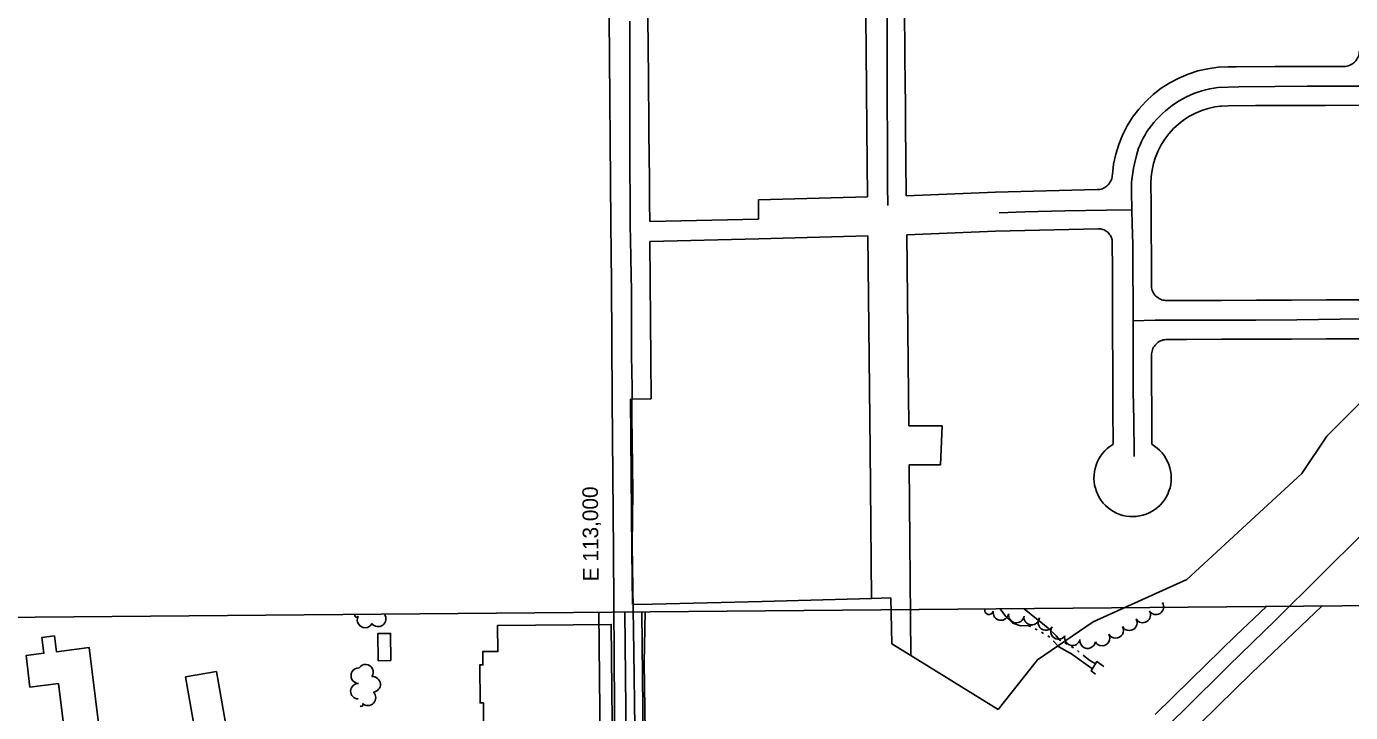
# Model space of a CAD drawing. Extents: x -2233 to 187241, y 4582 to 150524.
# Drawn here: x 112255 to 113957, y 59941 to 60823 of the extents above; entities that cross this region are included whole.
import ezdxf

# ---------------------------------------------------------------- set-up
doc = ezdxf.new("R2010")
doc.units = 0
for name, color, linetype in [('60', 7, 'Continuous'), ('BLDG', 7, 'Continuous'), ('CULVERT', 7, 'Continuous'), ('GE_X_CL_2000', 7, 'Continuous'), ('GRID', 7, 'Continuous'), ('INTERSTATE', 7, 'Continuous'), ('ROAD', 7, 'Continuous'), ('RW_X_Fee_RW', 7, 'Continuous'), ('TREES', 7, 'Continuous'), ('WATER', 7, 'Continuous')]:
    doc.layers.add(name, color=color, linetype=linetype)

msp = doc.modelspace()

# ---------------------------------------------------------------- linework, layer by layer
at = {"layer": '60'}
msp.add_line((109991.1, 60043.6), (114990.9, 60087.2), dxfattribs=at)
at = {"layer": 'BLDG'}
for points in [[(113008.4, 59888.4), (113006.8, 60054.3), (112860.7, 60052.9), (112861, 60019.4), (112841.6, 60019.3), (112841.8, 60002.2), (112837.7, 60002.2), (112838.2, 59953.3), (112842.3, 59953.4), (112842.7, 59912.5)], [(112323.8, 59752.8), (112295.8, 59978.3), (112259.2, 59973.7), (112254.2, 60014.3), (112277.2, 60017.2), (112274.7, 60037.5), (112290.8, 60039.5), (112293.3, 60019.1), (112335.5, 60024.4), (112351.4, 59896.2)]]:
    msp.add_lwpolyline(points, dxfattribs=at)
for points in [[(112723.4, 60007.8), (112722.9, 60042.7), (112706.6, 60042.5), (112707.1, 60007.6)], [(112499, 59993.6), (112511.8, 59920.6), (112472.2, 59913.6), (112459.4, 59986.7)]]:
    msp.add_lwpolyline(points, close=True, dxfattribs=at)
at = {"layer": 'CULVERT'}
msp.add_lwpolyline([(113640, 60000.1), (113631.1, 60006.5), (113624.1, 59994.4), (113629.7, 59990.2)], dxfattribs=at)
at = {"layer": 'GE_X_CL_2000'}
for points in [[(113361.5, 60852.7), (113361.8, 60818.3), (113361.5, 60783.6), (113361.4, 60745.1), (113361.8, 60710), (113362.1, 60693.8), (113362.2, 60664.6), (113362.2, 60618.9), (113362.5, 60593.1)], [(113030.5, 60830.1), (113030.8, 60787.7), (113030.8, 60743.9), (113030.7, 60700.9), (113030.7, 60644.3), (113031.2, 60597), (113031.2, 60566.1), (113031.6, 60550.3), (113032, 60524.8), (113033, 60482.9), (113032.6, 60442.8), (113033, 60399.9), (113033.5, 60359), (113033.4, 60331.5), (113033.4, 60322.1), (113034.7, 60225), (113033.8, 60156.2), (113036, 60018.9), (113036.9, 59922.4), (113037.7, 59833.1), (113038, 59732.7), (113039.2, 59659.9), (113041.5, 59583.1), (113041.4, 59538.4)], [(113676.2, 60587.4), (113675.7, 60610.6), (113675.8, 60616.7), (113676, 60622.7), (113676.6, 60628.7), (113677.3, 60634.7), (113678.3, 60640.7), (113679.5, 60646.6), (113682.1, 60657.2), (113683.5, 60661.8), (113685, 60666.4), (113686.8, 60670.9), (113688.7, 60675.3), (113690.9, 60679.6), (113693.2, 60683.8), (113695.7, 60687.9), (113698.4, 60691.9), (113701.3, 60695.8), (113704.4, 60699.5), (113707.9, 60703.6), (113711.7, 60707.4), (113715.5, 60711.2), (113719.6, 60714.7), (113723.7, 60718.1), (113728, 60721.4), (113732.5, 60724.4), (113737, 60727.3), (113741.6, 60730), (113746.4, 60732.4), (113751.2, 60734.6), (113756.1, 60736.7), (113761.1, 60738.6), (113766.1, 60740.2), (113771.3, 60741.7), (113776.4, 60742.9), (113781.7, 60743.9), (113786.9, 60744.7), (113813.8, 60745.5), (113860.1, 60746.1), (113901.9, 60746.2), (113945.8, 60746.2), (113975.7, 60746.4)], [(113505.6, 60583.3), (113538.5, 60584.7), (113590, 60586.1), (113643.6, 60587), (113676.2, 60587.4)], [(113676.2, 60587.4), (113676.5, 60569.4), (113677.6, 60542.9), (113677.6, 60524.8), (113677.5, 60505.2), (113678.1, 60473.9), (113677.8, 60444.6)], [(113677.8, 60444.6), (113706.1, 60445.6), (113747.9, 60445.3), (113835.8, 60445.4), (113888.2, 60446.1), (113944.1, 60446.6), (113991, 60447), (114010.2, 60446.1), (114026.6, 60446.2), (114078.5, 60446.5), (114086.5, 60446.8), (114094.5, 60447.3), (114102.5, 60448.1), (114110.4, 60449.2), (114117.4, 60451.1), (114124.2, 60453.7), (114130.9, 60457), (114137.2, 60460.8), (114143.2, 60465.2), (114148.7, 60470), (114153.7, 60475.3)], [(113677.8, 60444.6), (113677.9, 60401.4), (113678.1, 60357.4), (113678.5, 60331.5), (113678.6, 60320.8), (113679.1, 60270.1)], [(113973.9, 60171.5), (113918.6, 60116.8), (113861.4, 60060.3), (113800.5, 60000.9), (113743.9, 59944.7), (113689.6, 59892), (113636.5, 59840.6), (113573.6, 59779.7), (113509.2, 59718), (113438.7, 59653.3), (113379, 59599.4), (113344.7, 59567.8), (113332.6, 59556.6), (113316, 59541.3), (113301.8, 59528.7), (113254.1, 59486.6), (113202.8, 59441.5), (113191.5, 59431.1), (113123.8, 59370.9), (113063.3, 59318.1), (113037.7, 59296.4), (113006.2, 59273.3), (112963.6, 59238.9), (112917.8, 59201.4)]]:
    msp.add_lwpolyline(points, dxfattribs=at)
at = {"layer": 'GRID'}
for p, q in [((114990.9, 60087.2), (109991.1, 60043.6)), ((112991, 60069.8), (113014.5, 57372.1))]:
    msp.add_line(p, q, dxfattribs=at)
at = {"layer": 'INTERSTATE'}
for points in [[(113849.6, 60077.3), (113810.1, 60040.2), (113752, 59983.4), (113706.2, 59938.4)], [(113742.2, 59905.3), (113830.5, 59992), (113920.7, 60077.9)]]:
    msp.add_lwpolyline(points, dxfattribs=at)
at = {"layer": 'ROAD'}
for points in [[(113024.2, 60070.1), (113025.6, 59946.3), (113027, 59785), (113028.4, 59650.9), (113028.7, 59574.6), (113028.8, 59570.9)], [(113046.2, 60070.3), (113047.5, 59946.6), (113049, 59785.2), (113050.3, 59651), (113050.6, 59597.7)], [(113052.3, 59703.2), (113051, 59886.8), (113049.2, 60005.1), (113050.4, 60070.3)]]:
    msp.add_lwpolyline(points, dxfattribs=at)
at = {"layer": 'RW_X_Fee_RW'}
for p, q in [((113700.9, 60595.7), (113700.7, 60620.9)), ((113336.1, 60604), (113196.1, 60600.2)), ((113196.3, 60575.2), (113196.1, 60600.2)), ((113500.9, 60610.1), (113386.1, 60605.3)), ((113500.9, 60610.1), (113631.6, 60613.3)), ((113701.3, 60490.6), (113700.9, 60595.7)), ((113056.3, 60572.3), (113196.3, 60575.2)), ((113196.6, 60550), (113056.6, 60546.5)), ((113056.6, 60546.5), (113058.1, 60344.4)), ((113336.7, 60553.7), (113196.6, 60550)), ((113336.7, 60553.7), (113339.6, 60279.2)), ((113500.8, 60559.9), (113386.7, 60555)), ((113386.7, 60555), (113389.3, 60309.4)), ((113500.8, 60559.9), (113632.9, 60563.1)), ((113031.6, 60343.7), (113058.1, 60344.4)), ((113432.3, 60309.6), (113389.3, 60309.4)), ((113432.3, 60309.6), (113430.2, 60259.6)), ((113927, 60296.4), (113894.8, 60248.3)), ((113339.6, 60279.2), (113341.3, 60087.7)), ((113430.2, 60259.6), (113389.8, 60259.4)), ((113389.8, 60259.4), (113392, 60014.4)), ((113894.8, 60248.3), (113747, 60112.1)), ((113747, 60112.1), (113626.7, 60057.7)), ((113366.3, 60088.3), (113367.5, 60029.4)), ((113626.7, 60057.7), (113554.9, 60008.6)), ((113554.9, 60008.6), (113504.4, 59945))]:
    msp.add_line(p, q, dxfattribs=at)
for points in [[(113003.7, 60873), (113004, 60835.6), (113006.3, 60570.5), (113007, 60493.1)], [(113053.6, 60873.8), (113054.4, 60796.5), (113054.7, 60756.5), (113055.2, 60696.5), (113055.7, 60646.5), (113055.8, 60636.5), (113056.1, 60596.5), (113056.3, 60572.3)], [(113336.1, 60604), (113335.3, 60691.7), (113334.9, 60741.7), (113334.4, 60792.5), (113334.1, 60834.5), (113333.7, 60880)], [(113384.9, 60741.8), (113384.4, 60791.7), (113384, 60842.2), (113383.7, 60880.4), (113383.6, 60882.2)], [(113949.1, 60771.7), (113950.8, 60771.8), (113952.5, 60772), (113954.2, 60772.4), (113955.9, 60773), (113957.5, 60773.6), (113959, 60774.4), (113960.4, 60775.4), (113961.8, 60776.4), (113963.1, 60777.6), (113964.2, 60778.9), (113965.3, 60780.2), (113966.2, 60781.7), (113967, 60783.2), (113967.6, 60784.8), (113968.1, 60786.5), (113968.5, 60788.2), (113968.7, 60789.9), (113968.8, 60791.6)], [(113800.2, 60771.2), (113787.1, 60770.6), (113774.1, 60768.8), (113761.2, 60765.9), (113748.7, 60761.9), (113736.6, 60756.8), (113725, 60750.7), (113714, 60743.6), (113703.6, 60735.5), (113694.1, 60726.7), (113685.2, 60716.8), (113677.2, 60706.3), (113670.4, 60695.4), (113664.3, 60683.5), (113659.4, 60671.3), (113655.6, 60659.1), (113652.8, 60645.9), (113651.2, 60632.9)], [(113800.2, 60771.2), (113810.2, 60771.2), (113860.2, 60771.4), (113910.2, 60771.6), (113949.1, 60771.7)], [(113384.9, 60741.8), (113385, 60730.7), (113385.3, 60696.8), (113385.7, 60651.8), (113386.1, 60605.3)], [(113800.4, 60721.2), (113791.7, 60720.8), (113790.4, 60720.6), (113783, 60719.6), (113774.5, 60717.7), (113766.2, 60715.1), (113758.1, 60711.7), (113750.4, 60707.6), (113743.1, 60702.9), (113736.2, 60697.6), (113729.8, 60691.7), (113723.9, 60685.2), (113718.6, 60678.3), (113714, 60670.9), (113710, 60663.1), (113706.6, 60655.1), (113704, 60646.7), (113702.2, 60638.2), (113701.1, 60629.6), (113700.7, 60620.9)], [(113800.4, 60721.2), (113835.4, 60721.3), (113880.4, 60721.5), (113925.4, 60721.6), (113970.4, 60721.8), (113994.2, 60721.9)], [(113631.6, 60613.3), (113633.3, 60613.4), (113635, 60613.6), (113636.7, 60614), (113638.3, 60614.5), (113639.8, 60615.2), (113641.3, 60616), (113642.8, 60616.9), (113644.1, 60618), (113645.3, 60619.1), (113646.5, 60620.4), (113647.5, 60621.7), (113648.4, 60623.2), (113649.2, 60624.7), (113649.9, 60626.2), (113650.4, 60627.8), (113650.8, 60629.5), (113651.1, 60631.2), (113651.2, 60632.9)], [(113651, 60545.5), (113651, 60547), (113650.8, 60548.6), (113650.4, 60550.1), (113649.9, 60551.6), (113649.3, 60553.1), (113648.6, 60554.4), (113647.7, 60555.8), (113646.7, 60557), (113645.7, 60558.1), (113644.5, 60559.2), (113643.2, 60560.1), (113641.9, 60560.9), (113640.5, 60561.6), (113639.1, 60562.2), (113637.5, 60562.6), (113636, 60562.9), (113634.5, 60563.1), (113632.9, 60563.1)], [(113651.2, 60501.6), (113651.2, 60510.5), (113651, 60545.5)], [(113651.2, 60501.6), (113651.4, 60465.4), (113651.4, 60447.4), (113651.4, 60445.4)], [(113013.7, 59558.9), (113012.1, 59785.5), (113011.9, 59815.5), (113010, 60079.5), (113009.5, 60148.5), (113008.1, 60343.5), (113007, 60493.1)], [(113701.3, 60490.6), (113701.4, 60488.9), (113701.6, 60487.1), (113702, 60485.4), (113702.5, 60483.8), (113703.2, 60482.1), (113704, 60480.6), (113704.9, 60479.1), (113706, 60477.8), (113707.2, 60476.5), (113708.5, 60475.3), (113709.9, 60474.2), (113711.3, 60473.3), (113712.9, 60472.5), (113714.5, 60471.8), (113716.2, 60471.3), (113717.9, 60471), (113719.6, 60470.7), (113721.4, 60470.7)], [(113721.4, 60470.7), (113746.4, 60470.8), (113791.4, 60470.9), (113836.4, 60471.1), (113881.4, 60471.2), (113926.4, 60471.4), (113971.4, 60471.5), (114016.4, 60471.7), (114061.4, 60471.9), (114106.4, 60472)], [(113651.4, 60445.4), (113651.5, 60420.4), (113651.6, 60393.4), (113651.7, 60375.4), (113651.8, 60339.4), (113651.9, 60330.4), (113652, 60285.9)], [(113721.5, 60420.7), (113719.8, 60420.6), (113718.1, 60420.3), (113716.4, 60420), (113714.7, 60419.4), (113713.1, 60418.8), (113711.5, 60417.9), (113710.1, 60417), (113708.7, 60415.9), (113707.4, 60414.8), (113706.2, 60413.5), (113705.2, 60412.1), (113704.2, 60410.6), (113703.4, 60409.1), (113702.8, 60407.4), (113702.3, 60405.8), (113701.9, 60404.1), (113701.7, 60402.3), (113701.6, 60400.6)], [(113721.5, 60420.7), (113746.5, 60420.8), (113791.5, 60420.9), (113836.5, 60421.1), (113881.5, 60421.2), (113926.5, 60421.4), (113971.5, 60421.5), (114016.5, 60421.7)], [(113701.6, 60400.6), (113702, 60295.6), (113701.9, 60285.9)], [(113927, 60296.4), (113971.8, 60341.5), (114016.7, 60386.7)], [(113031.6, 60343.7), (113033.3, 60148.8), (113033.9, 60079.8)], [(113652, 60285.9), (113651.6, 60285.6), (113648.1, 60283), (113644.7, 60280.3), (113641.6, 60277.4), (113638.7, 60274.1), (113636.1, 60270.7), (113633.8, 60267), (113631.8, 60263.1), (113630.2, 60259.1), (113629, 60254.9), (113628.1, 60250.7), (113627.6, 60246.4), (113627.4, 60242.1), (113627.7, 60237.8), (113628.3, 60233.5), (113629.3, 60229.3), (113630.6, 60225.1), (113632.3, 60221.2), (113634.4, 60217.3), (113636.7, 60213.7), (113639.4, 60210.3), (113642.4, 60207.1), (113645.6, 60204.3), (113649, 60201.7), (113652.7, 60199.4), (113656.6, 60197.4), (113660.6, 60195.8), (113664.7, 60194.5), (113669, 60193.6), (113673.3, 60193.1), (113677.6, 60192.9), (113681.9, 60193.2), (113686.2, 60193.8), (113690.4, 60194.7), (113694.5, 60196.1), (113698.5, 60197.8), (113702.4, 60199.8), (113706, 60202.1), (113709.4, 60204.8), (113712.6, 60207.8), (113715.5, 60211), (113718.1, 60214.4), (113720.4, 60218.1), (113722.4, 60221.9), (113724, 60225.9), (113725.3, 60230.1), (113726.2, 60234.3), (113726.7, 60238.6), (113726.9, 60242.9), (113726.7, 60247.3), (113726.1, 60251.6), (113725.1, 60255.8), (113723.8, 60259.9), (113722.1, 60263.9), (113720.1, 60267.7), (113717.8, 60271.4), (113715.1, 60274.8), (113712.2, 60278), (113709, 60280.9), (113705.5, 60283.5), (113701.9, 60285.9)], [(113366.3, 60088.3), (113341.3, 60087.7), (113200.7, 60083.9)], [(113200.7, 60083.9), (113060, 60080.4), (113033.9, 60079.8)], [(113504.4, 59945), (113392, 60014.4), (113367.5, 60029.4)]]:
    msp.add_lwpolyline(points, dxfattribs=at)
at = {"layer": 'TREES'}
for centre, radius, start, end in [((113492.6, 60072.6), 5.63, 164.9683, 344.9683), ((113507.9, 60069.6), 10, 170.6126, 350.6126), ((113690.2, 60066.5), 10, 211.5384, 31.5384), ((113707.2, 60077), 10, 212.1213, 32.1213), ((112679.3, 60065.9), 2.36, 151.7857, 331.7857), ((112690.2, 60060.1), 10, 151.7857, 331.7857), ((112707, 60061.4), 10, 216.9335, 36.9335), ((113527.7, 60066.3), 10, 170.6482, 350.6482), ((113547.5, 60063.7), 10, 174.1626, 354.1626), ((113565.6, 60056.9), 10, 144.8036, 324.8036), ((113672.9, 60056.4), 10, 209.3156, 29.3156), ((113581.9, 60045.3), 10, 144.8036, 324.8036), ((113599.8, 60037.2), 10, 166.3546, 346.3546), ((113638, 60036.8), 10, 209.3156, 29.3156), ((113655.5, 60046.6), 10, 209.3156, 29.3156), ((113619.4, 60033.4), 10, 171.406, 351.406), ((112690.7, 59992.8), 10, 325.7179, 145.7179), ((112682.1, 59988.4), 10, 88.2567, 268.2567), ((112699.9, 59977.2), 10, 275.5104, 95.5104), ((112681.6, 59968.4), 10, 88.5793, 268.5793), ((112685.4, 59951.2), 2.28, 223.7837, 43.7837), ((112693.9, 59960), 10, 226.2103, 46.2103)]:
    msp.add_arc(centre, radius, start, end, dxfattribs=at)
at = {"layer": 'WATER'}
for p, q in [((113554.6, 60047.2), (113551.9, 60048.8)), ((113562.8, 60042.6), (113560, 60044.2)), ((113590.2, 60030.4), (113593, 60028.9)), ((113598.4, 60025.8), (113601, 60024.1))]:
    msp.add_line(p, q, dxfattribs=at)
for points in [[(113546.3, 60051.5), (113543.9, 60052.5), (113542, 60052.8), (113533.2, 60052.6), (113523.1, 60056), (113513.7, 60064.9), (113506.9, 60074.3)], [(113537.9, 60074.5), (113553.8, 60061.4), (113559.4, 60057), (113568.6, 60049.3), (113578.8, 60039.7), (113584.2, 60033.6), (113584.7, 60033.3)], [(113570.7, 60037.8), (113570, 60038.5), (113568.2, 60039.6)], [(113625.6, 59997), (113623, 59998.7), (113597.2, 60017.4), (113596.9, 60017.5), (113582.4, 60025.5), (113575.1, 60033.2)], [(113606.2, 60020.6), (113606.6, 60020.2), (113608.6, 60018.7)], [(113613.5, 60014.8), (113621.1, 60008.8), (113629.6, 60003.8)]]:
    msp.add_lwpolyline(points, dxfattribs=at)

# ---------------------------------------------------------------- texts
at = {"layer": 'GRID'}
msp.add_text('E 113,000', height=20, rotation=90.5, dxfattribs=at).set_placement((112990.6, 60109.8))

doc.saveas('drawing.dxf')
